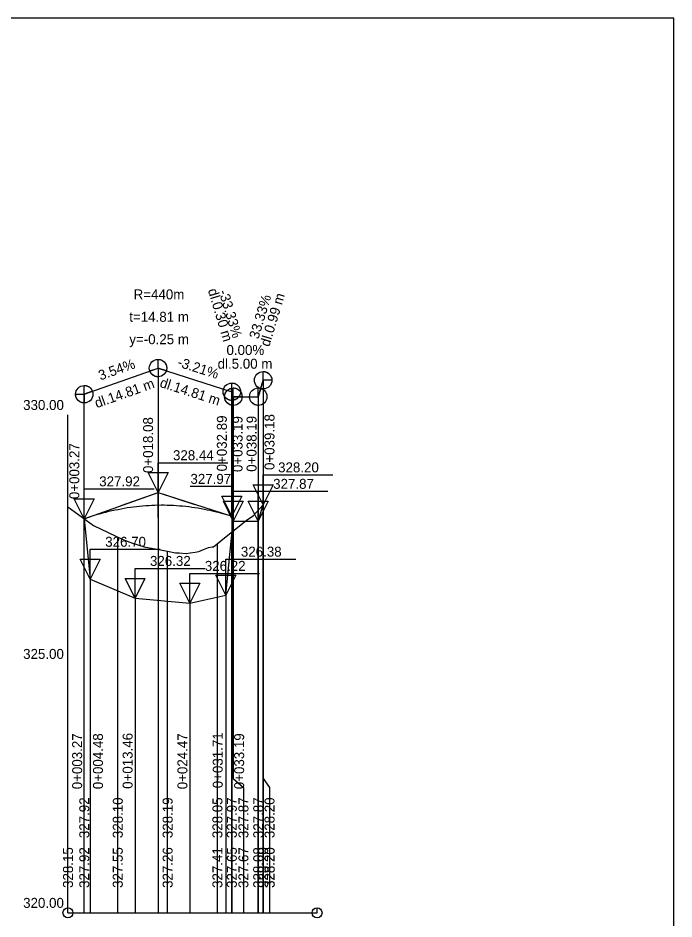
# Model space of a CAD drawing. Extents: x -559854 to -559644, y -1162908 to -1162611.
# Drawn here: x -559776.1 to -559644.4, y -1162791.6 to -1162610.6 of the extents above; entities that cross this region are included whole.
import ezdxf

# ---------------------------------------------------------------- set-up
doc = ezdxf.new("R2010")
doc.units = 0
for name, color, linetype in [('13', 7, 'Continuous'), ('14', 7, 'Continuous'), ('16', 7, 'Continuous'), ('46', 7, 'Continuous'), ('56', 7, 'Continuous'), ('8', 7, 'Continuous')]:
    doc.layers.add(name, color=color, linetype=linetype)

msp = doc.modelspace()

# ---------------------------------------------------------------- linework, layer by layer
for p, q in [((-559644.4, -1162610.63), (-559854.4, -1162610.63)), ((-559644.4, -1162907.63), (-559644.4, -1162610.63)), ((-559755.37, -1162708.56), (-559747.96, -1162705.94)), ((-559747.96, -1162710.94), (-559747.96, -1162705.94)), ((-559747.96, -1162705.94), (-559740.56, -1162708.31)), ((-559727.85, -1162711.69), (-559726.86, -1162708.38)), ((-559726.86, -1162790.35), (-559726.86, -1162708.35)), ((-559766.04, -1162790.35), (-559766.04, -1162708.85)), ((-559727.85, -1162790.35), (-559727.85, -1162709.55)), ((-559762.77, -1162790.35), (-559762.77, -1162711.15)), ((-559762.77, -1162790.35), (-559762.77, -1162711.15)), ((-559762.77, -1162711.19), (-559762.77, -1162711.19)), ((-559762.77, -1162711.19), (-559761.56, -1162723.33)), ((-559762.77, -1162711.19), (-559762.77, -1162711.19)), ((-559734.33, -1162726.55), (-559732.85, -1162711.69)), ((-559733.15, -1162710.69), (-559733.15, -1162710.69)), ((-559733.15, -1162710.69), (-559732.85, -1162711.69)), ((-559733.15, -1162710.69), (-559733.15, -1162710.69)), ((-559732.85, -1162711.69), (-559727.85, -1162711.69)), ((-559733.15, -1162790.35), (-559733.15, -1162713.85)), ((-559733.15, -1162790.35), (-559733.15, -1162713.85)), ((-559732.85, -1162763.37), (-559732.85, -1162713.65)), ((-559756.04, -1162790.35), (-559756.04, -1162714.85)), ((-559736.04, -1162790.35), (-559736.04, -1162716.25)), ((-559746.04, -1162790.35), (-559746.04, -1162717.75)), ((-559761.56, -1162723.33), (-559752.58, -1162727.17)), ((-559741.57, -1162728.17), (-559734.33, -1162726.55)), ((-559752.58, -1162727.17), (-559741.57, -1162728.17)), ((-559725.54, -1162790.35), (-559725.54, -1162765.15))]:
    msp.add_line(p, q)
for points in [[(-559766.04, -1162708.82), (-559760.9, -1162712.54), (-559755.05, -1162715.37), (-559753.07, -1162716.12), (-559753.07, -1162716.12), (-559750.72, -1162716.84), (-559747.47, -1162717.47), (-559745.74, -1162717.79), (-559744.46, -1162718.02), (-559744.01, -1162718.03), (-559743.74, -1162718.03), (-559742.34, -1162718.19), (-559742.27, -1162718.18), (-559741.5, -1162718.07), (-559740.54, -1162717.89), (-559739.78, -1162717.75), (-559738.81, -1162717.37), (-559737.82, -1162716.98), (-559737.07, -1162716.87), (-559736.83, -1162716.83), (-559735.34, -1162715.65), (-559730.26, -1162711.57), (-559728.82, -1162710.52), (-559727.58, -1162709.22), (-559726.82, -1162708.34)], [(-559762.77, -1162711.19), (-559762.15, -1162710.97), (-559761.54, -1162710.77), (-559760.92, -1162710.57), (-559760.3, -1162710.38), (-559759.68, -1162710.2), (-559759.07, -1162710.03), (-559758.45, -1162709.87), (-559757.83, -1162709.71), (-559757.22, -1162709.57), (-559756.6, -1162709.43), (-559755.98, -1162709.31), (-559755.37, -1162709.19), (-559754.75, -1162709.08), (-559754.13, -1162708.97), (-559753.51, -1162708.88), (-559752.9, -1162708.8), (-559752.28, -1162708.72), (-559751.66, -1162708.66), (-559751.05, -1162708.6), (-559750.43, -1162708.55), (-559749.81, -1162708.51), (-559749.19, -1162708.47), (-559748.58, -1162708.45), (-559747.34, -1162708.43), (-559746.73, -1162708.43), (-559746.11, -1162708.44), (-559745.49, -1162708.46), (-559744.87, -1162708.49), (-559744.26, -1162708.53), (-559743.64, -1162708.58), (-559743.02, -1162708.63), (-559742.41, -1162708.69), (-559741.79, -1162708.77), (-559741.17, -1162708.85), (-559740.56, -1162708.94), (-559739.94, -1162709.03), (-559739.32, -1162709.14), (-559738.7, -1162709.26), (-559738.09, -1162709.38), (-559737.47, -1162709.51), (-559736.85, -1162709.66), (-559736.24, -1162709.81), (-559735.62, -1162709.96), (-559735, -1162710.13), (-559734.38, -1162710.31), (-559733.77, -1162710.49), (-559733.15, -1162710.69)], [(-559762.77, -1162711.19), (-559762.15, -1162710.97), (-559761.54, -1162710.77), (-559760.92, -1162710.57), (-559760.3, -1162710.38), (-559759.68, -1162710.2), (-559759.07, -1162710.03), (-559758.45, -1162709.87), (-559757.83, -1162709.71), (-559757.22, -1162709.57), (-559756.6, -1162709.43), (-559755.98, -1162709.31), (-559755.37, -1162709.19), (-559754.75, -1162709.08), (-559754.13, -1162708.97), (-559753.51, -1162708.88), (-559752.9, -1162708.8), (-559752.28, -1162708.72), (-559751.66, -1162708.66), (-559751.05, -1162708.6), (-559750.43, -1162708.55), (-559749.81, -1162708.51), (-559749.19, -1162708.47), (-559748.58, -1162708.45), (-559747.34, -1162708.43), (-559746.73, -1162708.43), (-559746.11, -1162708.44), (-559745.49, -1162708.46), (-559744.87, -1162708.49), (-559744.26, -1162708.53), (-559743.64, -1162708.58), (-559743.02, -1162708.63), (-559742.41, -1162708.69), (-559741.79, -1162708.77), (-559741.17, -1162708.85), (-559740.56, -1162708.94), (-559739.94, -1162709.03), (-559739.32, -1162709.14), (-559738.7, -1162709.26), (-559738.09, -1162709.38), (-559737.47, -1162709.51), (-559736.85, -1162709.66), (-559736.24, -1162709.81), (-559735.62, -1162709.96), (-559735, -1162710.13), (-559734.38, -1162710.31), (-559733.77, -1162710.49), (-559733.15, -1162710.69)], [(-559725.54, -1162765.15), (-559726.82, -1162763.37), (-559726.82, -1162708.34)]]:
    msp.add_lwpolyline(points)
for centre in [(-559766.04, -1162790.35), (-559716.04, -1162790.35)]:
    msp.add_circle(centre, 1)
at = {"layer": '14'}
for p, q in [((-559762.77, -1162686.19), (-559747.96, -1162680.94)), ((-559747.96, -1162680.94), (-559747.96, -1162790.35)), ((-559747.96, -1162680.94), (-559733.15, -1162685.69)), ((-559727.85, -1162686.69), (-559726.86, -1162683.38)), ((-559726.86, -1162683.38), (-559726.86, -1162790.35)), ((-559762.77, -1162686.19), (-559762.77, -1162686.19)), ((-559733.15, -1162685.69), (-559733.15, -1162790.35)), ((-559733.15, -1162685.69), (-559732.85, -1162686.69)), ((-559732.85, -1162686.69), (-559732.85, -1162763.37)), ((-559732.85, -1162686.69), (-559727.85, -1162686.69)), ((-559727.85, -1162686.69), (-559727.85, -1162790.35)), ((-559762.77, -1162711.19), (-559747.96, -1162705.94)), ((-559747.96, -1162705.94), (-559747.96, -1162790.35)), ((-559747.96, -1162705.94), (-559733.15, -1162710.69)), ((-559727.85, -1162711.69), (-559726.86, -1162708.38)), ((-559727.85, -1162711.69), (-559726.86, -1162708.38)), ((-559727.85, -1162711.69), (-559726.86, -1162708.38)), ((-559726.86, -1162708.38), (-559726.86, -1162790.35)), ((-559762.77, -1162711.19), (-559761.56, -1162723.33)), ((-559762.77, -1162711.19), (-559762.77, -1162711.19)), ((-559762.77, -1162711.19), (-559762.77, -1162711.19)), ((-559762.77, -1162711.19), (-559762.77, -1162711.19)), ((-559762.77, -1162711.19), (-559761.56, -1162723.33)), ((-559762.77, -1162711.19), (-559762.77, -1162711.19)), ((-559762.77, -1162711.19), (-559761.56, -1162723.33)), ((-559734.33, -1162726.55), (-559732.85, -1162711.69)), ((-559734.33, -1162726.55), (-559732.85, -1162711.69)), ((-559734.33, -1162726.55), (-559732.85, -1162711.69)), ((-559733.15, -1162710.69), (-559733.15, -1162710.69)), ((-559733.15, -1162710.69), (-559732.85, -1162711.69)), ((-559733.15, -1162710.69), (-559733.15, -1162710.69)), ((-559733.15, -1162710.69), (-559732.85, -1162711.69)), ((-559733.15, -1162710.69), (-559733.15, -1162790.35)), ((-559733.15, -1162710.69), (-559732.85, -1162711.69)), ((-559732.85, -1162711.69), (-559727.85, -1162711.69)), ((-559732.85, -1162711.69), (-559727.85, -1162711.69)), ((-559732.85, -1162711.69), (-559732.85, -1162763.37)), ((-559732.85, -1162711.69), (-559727.85, -1162711.69)), ((-559732.85, -1162711.69), (-559732.85, -1162763.37)), ((-559727.85, -1162711.69), (-559727.85, -1162790.35)), ((-559761.56, -1162723.33), (-559752.58, -1162727.17)), ((-559761.56, -1162723.33), (-559761.56, -1162790.35)), ((-559761.56, -1162723.33), (-559752.58, -1162727.17)), ((-559741.57, -1162728.17), (-559734.33, -1162726.55)), ((-559741.57, -1162728.17), (-559734.33, -1162726.55)), ((-559734.33, -1162726.55), (-559734.33, -1162790.35)), ((-559752.58, -1162727.17), (-559741.57, -1162728.17)), ((-559752.58, -1162727.17), (-559752.58, -1162790.35)), ((-559752.58, -1162727.17), (-559741.57, -1162728.17)), ((-559741.57, -1162728.17), (-559741.57, -1162790.35))]:
    msp.add_line(p, q, dxfattribs=at)
for points in [[(-559762.77, -1162711.19), (-559762.15, -1162710.97), (-559761.54, -1162710.77), (-559760.92, -1162710.57), (-559760.3, -1162710.38), (-559759.68, -1162710.2), (-559759.07, -1162710.03), (-559758.45, -1162709.87), (-559757.83, -1162709.71), (-559757.22, -1162709.57), (-559756.6, -1162709.43), (-559755.98, -1162709.31), (-559755.37, -1162709.19), (-559754.75, -1162709.08), (-559754.13, -1162708.97), (-559753.51, -1162708.88), (-559752.9, -1162708.8), (-559752.28, -1162708.72), (-559751.66, -1162708.66), (-559751.05, -1162708.6), (-559750.43, -1162708.55), (-559749.81, -1162708.51), (-559749.19, -1162708.47), (-559748.58, -1162708.45), (-559747.34, -1162708.43), (-559746.73, -1162708.43), (-559746.11, -1162708.44), (-559745.49, -1162708.46), (-559744.87, -1162708.49), (-559744.26, -1162708.53), (-559743.64, -1162708.58), (-559743.02, -1162708.63), (-559742.41, -1162708.69), (-559741.79, -1162708.77), (-559741.17, -1162708.85), (-559740.56, -1162708.94), (-559739.94, -1162709.03), (-559739.32, -1162709.14), (-559738.7, -1162709.26), (-559738.09, -1162709.38), (-559737.47, -1162709.51), (-559736.85, -1162709.66), (-559736.24, -1162709.81), (-559735.62, -1162709.96), (-559735, -1162710.13), (-559734.38, -1162710.31), (-559733.77, -1162710.49), (-559733.15, -1162710.69)], [(-559732.85, -1162763.37), (-559730.82, -1162765.15), (-559730.82, -1162790.35)]]:
    msp.add_lwpolyline(points, dxfattribs=at)
at = {"layer": '16'}
msp.add_lwpolyline([(-559762.77, -1162711.19), (-559762.15, -1162710.97), (-559761.54, -1162710.77), (-559760.92, -1162710.57), (-559760.3, -1162710.38), (-559759.68, -1162710.2), (-559759.07, -1162710.03), (-559758.45, -1162709.87), (-559757.83, -1162709.71), (-559757.22, -1162709.57), (-559756.6, -1162709.43), (-559755.98, -1162709.31), (-559755.37, -1162709.19), (-559754.75, -1162709.08), (-559754.13, -1162708.97), (-559753.51, -1162708.88), (-559752.9, -1162708.8), (-559752.28, -1162708.72), (-559751.66, -1162708.66), (-559751.05, -1162708.6), (-559750.43, -1162708.55), (-559749.81, -1162708.51), (-559749.19, -1162708.47), (-559748.58, -1162708.45), (-559747.34, -1162708.43), (-559746.73, -1162708.43), (-559746.11, -1162708.44), (-559745.49, -1162708.46), (-559744.87, -1162708.49), (-559744.26, -1162708.53), (-559743.64, -1162708.58), (-559743.02, -1162708.63), (-559742.41, -1162708.69), (-559741.79, -1162708.77), (-559741.17, -1162708.85), (-559740.56, -1162708.94), (-559739.94, -1162709.03), (-559739.32, -1162709.14), (-559738.7, -1162709.26), (-559738.09, -1162709.38), (-559737.47, -1162709.51), (-559736.85, -1162709.66), (-559736.24, -1162709.81), (-559735.62, -1162709.96), (-559735, -1162710.13), (-559734.38, -1162710.31), (-559733.77, -1162710.49), (-559733.15, -1162710.69)], dxfattribs=at)
at = {"layer": '46'}
for points in [[(-559747.96, -1162680.94), (-559747.96, -1162679.19), (-559747.85, -1162679.19), (-559747.74, -1162679.2), (-559747.63, -1162679.22), (-559747.52, -1162679.24), (-559747.41, -1162679.28), (-559747.3, -1162679.31), (-559747.2, -1162679.36), (-559747.1, -1162679.41), (-559747.01, -1162679.47), (-559746.91, -1162679.53), (-559746.83, -1162679.6), (-559746.74, -1162679.68), (-559746.66, -1162679.76), (-559746.59, -1162679.85), (-559746.52, -1162679.94), (-559746.46, -1162680.03), (-559746.41, -1162680.13), (-559746.36, -1162680.23), (-559746.32, -1162680.33), (-559746.28, -1162680.44), (-559746.25, -1162680.55), (-559746.23, -1162680.66), (-559746.22, -1162680.77), (-559746.21, -1162680.88), (-559746.21, -1162680.99), (-559746.22, -1162681.1), (-559746.23, -1162681.22), (-559746.25, -1162681.33), (-559746.28, -1162681.43), (-559746.29, -1162681.47), (-559747.96, -1162680.94), (-559747.96, -1162682.69), (-559748.07, -1162682.68), (-559748.18, -1162682.67), (-559748.29, -1162682.65), (-559748.4, -1162682.63), (-559748.51, -1162682.6), (-559748.62, -1162682.56), (-559748.72, -1162682.51), (-559748.82, -1162682.46), (-559748.91, -1162682.4), (-559749.01, -1162682.34), (-559749.09, -1162682.27), (-559749.18, -1162682.19), (-559749.26, -1162682.11), (-559749.33, -1162682.03), (-559749.4, -1162681.94), (-559749.46, -1162681.84), (-559749.51, -1162681.75), (-559749.56, -1162681.64), (-559749.6, -1162681.54), (-559749.61, -1162681.52)], [(-559726.86, -1162683.38), (-559726.86, -1162681.63), (-559726.75, -1162681.64), (-559726.63, -1162681.65), (-559726.52, -1162681.66), (-559726.41, -1162681.69), (-559726.31, -1162681.72), (-559726.2, -1162681.76), (-559726.1, -1162681.81), (-559726, -1162681.86), (-559725.9, -1162681.92), (-559725.81, -1162681.98), (-559725.72, -1162682.05), (-559725.64, -1162682.13), (-559725.56, -1162682.21), (-559725.49, -1162682.29), (-559725.42, -1162682.38), (-559725.36, -1162682.48), (-559725.31, -1162682.57), (-559725.26, -1162682.67), (-559725.21, -1162682.78), (-559725.18, -1162682.88), (-559725.15, -1162682.99), (-559725.13, -1162683.1), (-559725.12, -1162683.21), (-559725.11, -1162683.33), (-559725.11, -1162683.38), (-559726.86, -1162683.38), (-559726.86, -1162685.13), (-559726.97, -1162685.13), (-559727.08, -1162685.12), (-559727.19, -1162685.1), (-559727.3, -1162685.08), (-559727.36, -1162685.06)], [(-559762.77, -1162686.19), (-559762.77, -1162684.44), (-559762.66, -1162684.44), (-559762.55, -1162684.45), (-559762.44, -1162684.47), (-559762.33, -1162684.49), (-559762.22, -1162684.53), (-559762.12, -1162684.57), (-559762.01, -1162684.61), (-559761.91, -1162684.66), (-559761.82, -1162684.72), (-559761.73, -1162684.78), (-559761.64, -1162684.85), (-559761.55, -1162684.93), (-559761.48, -1162685.01), (-559761.4, -1162685.1), (-559761.34, -1162685.19), (-559761.28, -1162685.28), (-559761.22, -1162685.38), (-559761.17, -1162685.48), (-559761.13, -1162685.58), (-559761.12, -1162685.6), (-559762.77, -1162686.19), (-559762.77, -1162687.94), (-559762.88, -1162687.93), (-559763, -1162687.92), (-559763.11, -1162687.9), (-559763.22, -1162687.88), (-559763.32, -1162687.85), (-559763.43, -1162687.81), (-559763.53, -1162687.76), (-559763.63, -1162687.71), (-559763.73, -1162687.65), (-559763.82, -1162687.59), (-559763.91, -1162687.52), (-559763.99, -1162687.44), (-559764.07, -1162687.36), (-559764.14, -1162687.28), (-559764.21, -1162687.19), (-559764.27, -1162687.09), (-559764.32, -1162687), (-559764.37, -1162686.9), (-559764.41, -1162686.79), (-559764.45, -1162686.69), (-559764.48, -1162686.58), (-559764.5, -1162686.47), (-559764.51, -1162686.36), (-559764.52, -1162686.24), (-559764.52, -1162686.19)], [(-559733.15, -1162685.69), (-559733.15, -1162683.94), (-559733.04, -1162683.94), (-559732.92, -1162683.95), (-559732.81, -1162683.97), (-559732.7, -1162683.99), (-559732.6, -1162684.03), (-559732.49, -1162684.07), (-559732.39, -1162684.11), (-559732.29, -1162684.16), (-559732.19, -1162684.22), (-559732.1, -1162684.28), (-559732.01, -1162684.35), (-559731.93, -1162684.43), (-559731.85, -1162684.51), (-559731.78, -1162684.6), (-559731.71, -1162684.69), (-559731.65, -1162684.78), (-559731.6, -1162684.88), (-559731.55, -1162684.98), (-559731.51, -1162685.08), (-559731.47, -1162685.19), (-559731.44, -1162685.3), (-559731.42, -1162685.41), (-559731.41, -1162685.52), (-559731.4, -1162685.63), (-559731.4, -1162685.74), (-559731.41, -1162685.86), (-559731.42, -1162685.97), (-559731.44, -1162686.08), (-559731.47, -1162686.19), (-559731.51, -1162686.29), (-559731.55, -1162686.4), (-559731.6, -1162686.5), (-559731.65, -1162686.59), (-559731.71, -1162686.69), (-559731.78, -1162686.78), (-559731.85, -1162686.86), (-559731.93, -1162686.94), (-559732.01, -1162687.02), (-559732.1, -1162687.09), (-559732.19, -1162687.15), (-559732.29, -1162687.21), (-559732.39, -1162687.26), (-559732.49, -1162687.31), (-559732.6, -1162687.35), (-559732.65, -1162687.36), (-559733.15, -1162685.69), (-559733.15, -1162687.44), (-559733.26, -1162687.43), (-559733.37, -1162687.42), (-559733.48, -1162687.4), (-559733.59, -1162687.38), (-559733.7, -1162687.35), (-559733.81, -1162687.31), (-559733.91, -1162687.26), (-559734.01, -1162687.21), (-559734.1, -1162687.15), (-559734.2, -1162687.09), (-559734.28, -1162687.02), (-559734.37, -1162686.94), (-559734.44, -1162686.86), (-559734.52, -1162686.78), (-559734.58, -1162686.69), (-559734.65, -1162686.59), (-559734.7, -1162686.5), (-559734.75, -1162686.4), (-559734.79, -1162686.29), (-559734.83, -1162686.19), (-559734.85, -1162686.08), (-559734.88, -1162685.97), (-559734.89, -1162685.86), (-559734.9, -1162685.74), (-559734.9, -1162685.63), (-559734.89, -1162685.52), (-559734.88, -1162685.41), (-559734.85, -1162685.3), (-559734.83, -1162685.19), (-559734.82, -1162685.15)], [(-559732.85, -1162686.69), (-559732.85, -1162684.94), (-559732.74, -1162684.94), (-559732.62, -1162684.95), (-559732.51, -1162684.97), (-559732.4, -1162684.99), (-559732.3, -1162685.03), (-559732.19, -1162685.07), (-559732.09, -1162685.11), (-559731.99, -1162685.16), (-559731.89, -1162685.22), (-559731.8, -1162685.28), (-559731.71, -1162685.35), (-559731.63, -1162685.43), (-559731.55, -1162685.51), (-559731.48, -1162685.6), (-559731.41, -1162685.69), (-559731.35, -1162685.78), (-559731.3, -1162685.88), (-559731.25, -1162685.98), (-559731.21, -1162686.08), (-559731.17, -1162686.19), (-559731.14, -1162686.3), (-559731.12, -1162686.41), (-559731.11, -1162686.52), (-559731.1, -1162686.63), (-559731.1, -1162686.69), (-559732.85, -1162686.69), (-559732.85, -1162688.44), (-559732.96, -1162688.43), (-559733.07, -1162688.42), (-559733.18, -1162688.4), (-559733.29, -1162688.38), (-559733.4, -1162688.35), (-559733.51, -1162688.31), (-559733.61, -1162688.26), (-559733.71, -1162688.21), (-559733.8, -1162688.15), (-559733.9, -1162688.09), (-559733.98, -1162688.02), (-559734.07, -1162687.94), (-559734.14, -1162687.86), (-559734.22, -1162687.78), (-559734.28, -1162687.69), (-559734.35, -1162687.59), (-559734.4, -1162687.5), (-559734.45, -1162687.4), (-559734.49, -1162687.29), (-559734.53, -1162687.19), (-559734.55, -1162687.08), (-559734.58, -1162686.97), (-559734.59, -1162686.86), (-559734.6, -1162686.74), (-559734.6, -1162686.63), (-559734.59, -1162686.52), (-559734.58, -1162686.41), (-559734.55, -1162686.3), (-559734.53, -1162686.19), (-559734.49, -1162686.08), (-559734.45, -1162685.98), (-559734.4, -1162685.88), (-559734.35, -1162685.78), (-559734.28, -1162685.69), (-559734.22, -1162685.6), (-559734.14, -1162685.51), (-559734.07, -1162685.43), (-559733.98, -1162685.35), (-559733.9, -1162685.28), (-559733.8, -1162685.22), (-559733.71, -1162685.16), (-559733.61, -1162685.11), (-559733.51, -1162685.07), (-559733.4, -1162685.03), (-559733.35, -1162685.01)], [(-559727.85, -1162686.69), (-559727.85, -1162684.94), (-559727.74, -1162684.94), (-559727.62, -1162684.95), (-559727.51, -1162684.97), (-559727.4, -1162684.99), (-559727.35, -1162685.01), (-559727.85, -1162686.69), (-559727.85, -1162688.44), (-559727.96, -1162688.43), (-559728.07, -1162688.42), (-559728.18, -1162688.4), (-559728.29, -1162688.38), (-559728.4, -1162688.35), (-559728.51, -1162688.31), (-559728.61, -1162688.26), (-559728.71, -1162688.21), (-559728.8, -1162688.15), (-559728.9, -1162688.09), (-559728.98, -1162688.02), (-559729.07, -1162687.94), (-559729.14, -1162687.86), (-559729.22, -1162687.78), (-559729.28, -1162687.69), (-559729.35, -1162687.59), (-559729.4, -1162687.5), (-559729.45, -1162687.4), (-559729.49, -1162687.29), (-559729.53, -1162687.19), (-559729.55, -1162687.08), (-559729.58, -1162686.97), (-559729.59, -1162686.86), (-559729.6, -1162686.74), (-559729.6, -1162686.69)], [(-559747.96, -1162705.94), (-559749.96, -1162701.94), (-559745.96, -1162701.94)], [(-559726.86, -1162708.38), (-559728.86, -1162704.38), (-559724.86, -1162704.38)], [(-559733.15, -1162710.69), (-559735.15, -1162706.69), (-559731.15, -1162706.69)], [(-559762.77, -1162711.19), (-559764.77, -1162707.19), (-559760.77, -1162707.19)], [(-559762.77, -1162711.19), (-559764.77, -1162707.19), (-559760.77, -1162707.19)], [(-559732.85, -1162711.69), (-559734.85, -1162707.69), (-559730.85, -1162707.69)], [(-559732.85, -1162711.69), (-559734.85, -1162707.69), (-559730.85, -1162707.69)], [(-559727.85, -1162711.69), (-559729.85, -1162707.69), (-559725.85, -1162707.69)], [(-559761.56, -1162723.33), (-559763.56, -1162719.33), (-559759.56, -1162719.33)], [(-559734.33, -1162726.55), (-559736.33, -1162722.55), (-559732.33, -1162722.55)], [(-559752.58, -1162727.17), (-559754.58, -1162723.17), (-559750.58, -1162723.17)], [(-559741.57, -1162728.17), (-559743.57, -1162724.17), (-559739.57, -1162724.17)]]:
    msp.add_lwpolyline(points, close=True, dxfattribs=at)
for centre in [(-559747.96, -1162680.94), (-559726.86, -1162683.38), (-559762.77, -1162686.19), (-559733.15, -1162685.69), (-559732.85, -1162686.69), (-559727.85, -1162686.69)]:
    msp.add_circle(centre, 1.75, dxfattribs=at)
at = {"layer": '56'}
for p, q in [((-559766.04, -1162790.35), (-559766.04, -1162690.35)), ((-559766.04, -1162790.35), (-559766.04, -1162789.35)), ((-559716.04, -1162790.35), (-559716.04, -1162789.35)), ((-559766.04, -1162790.35), (-559716.04, -1162790.35))]:
    msp.add_line(p, q, dxfattribs=at)
at = {"layer": '8'}
for p, q in [((-559762.77, -1162711.19), (-559762.77, -1162686.19)), ((-559733.15, -1162710.69), (-559733.15, -1162685.69)), ((-559747.96, -1162705.94), (-559747.96, -1162699.94)), ((-559747.96, -1162699.94), (-559733.96, -1162699.94)), ((-559726.86, -1162708.38), (-559726.86, -1162702.38)), ((-559726.86, -1162702.38), (-559712.86, -1162702.38)), ((-559741.53, -1162704.69), (-559733.15, -1162704.69)), ((-559733.15, -1162710.69), (-559733.15, -1162704.69)), ((-559762.77, -1162711.19), (-559762.77, -1162705.19)), ((-559762.77, -1162705.19), (-559748.77, -1162705.19)), ((-559762.77, -1162711.19), (-559762.77, -1162705.19)), ((-559762.77, -1162705.19), (-559748.77, -1162705.19)), ((-559732.85, -1162711.69), (-559732.85, -1162705.69)), ((-559732.85, -1162705.69), (-559718.85, -1162705.69)), ((-559732.85, -1162711.69), (-559732.85, -1162705.69)), ((-559732.85, -1162705.69), (-559718.85, -1162705.69)), ((-559727.85, -1162711.69), (-559727.85, -1162705.69)), ((-559727.85, -1162705.69), (-559713.85, -1162705.69)), ((-559761.56, -1162723.33), (-559761.56, -1162717.33)), ((-559761.56, -1162717.33), (-559747.56, -1162717.33)), ((-559734.33, -1162726.55), (-559734.33, -1162719.31)), ((-559734.33, -1162719.31), (-559720.33, -1162719.31)), ((-559752.58, -1162727.17), (-559752.58, -1162721.17)), ((-559752.58, -1162721.17), (-559738.58, -1162721.17)), ((-559741.57, -1162728.17), (-559741.57, -1162722.17)), ((-559741.57, -1162722.17), (-559727.57, -1162722.17))]:
    msp.add_line(p, q, dxfattribs=at)

# ---------------------------------------------------------------- texts
for s, p in [('327.92', (-559761.77, -1162775.35)), ('327.92', (-559761.77, -1162775.35)), ('328.10', (-559755.04, -1162775.35)), ('328.19', (-559745.04, -1162775.35)), ('328.05', (-559735.04, -1162775.35)), ('327.97', (-559732.15, -1162775.35)), ('327.97', (-559732.15, -1162775.35)), ('327.87', (-559729.82, -1162775.35)), ('327.87', (-559726.85, -1162775.35)), ('328.20', (-559724.58, -1162775.35)), ('328.15', (-559765.04, -1162785.35)), ('327.55', (-559755.04, -1162785.35)), ('327.26', (-559745.04, -1162785.35)), ('327.65', (-559732.15, -1162785.35)), ('327.65', (-559732.15, -1162785.35)), ('328.08', (-559726.85, -1162785.35)), ('328.20', (-559725.86, -1162785.35)), ('328.20', (-559724.58, -1162785.35)), ('328.20', (-559724.54, -1162785.35)), ('327.92', (-559761.77, -1162785.35)), ('327.92', (-559761.77, -1162785.35)), ('327.41', (-559735.04, -1162785.35)), ('327.67', (-559729.82, -1162785.35))]:
    msp.add_text(s, height=2, rotation=90).set_placement(p)
at = {"layer": '13'}
for s, p in [('330.00', (-559775.04, -1162689.35)), ('330.00', (-559775.04, -1162689.35)), ('325.00', (-559775.04, -1162739.35)), ('320.00', (-559775.04, -1162789.35))]:
    msp.add_text(s, height=2, dxfattribs=at).set_placement(p)
at = {"layer": '16'}
for s, rotation, p in [('dl.0.30 m', 286.6992, (-559737.98, -1162665.28)), ('-33.33%', 286.6992, (-559735.81, -1162665.54)), ('33.33%', 73.3008, (-559727.81, -1162675.24)), ('dl.0.99 m', 73.3008, (-559725.63, -1162676.77)), ('3.54%', 19.5194, (-559759.52, -1162683.44)), ('-3.21%', 342.2168, (-559744.23, -1162680.56)), ('dl.14.81 m', 342.2168, (-559747.75, -1162684.68)), ('dl.14.81 m', 19.5194, (-559760.26, -1162689.01)), ('0+039.18', 90, (-559724.59, -1162701.41)), ('0+018.08', 90, (-559748.96, -1162702.02)), ('0+032.89', 90, (-559734.15, -1162701.69)), ('0+033.19', 90, (-559731, -1162701.82)), ('0+038.19', 90, (-559728.19, -1162701.77)), ('0+003.27', 90, (-559763.77, -1162707.26)), ('0+003.27', 90, (-559763.2, -1162765.53)), ('0+004.48', 90, (-559759.02, -1162765.52)), ('0+013.46', 90, (-559753.07, -1162765.45)), ('0+024.47', 90, (-559742.07, -1162765.53)), ('0+031.71', 90, (-559734.98, -1162765.33)), ('0+033.19', 90, (-559730.68, -1162765.52))]:
    msp.add_text(s, height=2, rotation=rotation, dxfattribs=at).set_placement(p)
for s, p in [('R=440m', (-559752.86, -1162667.14)), ('t=14.81 m', (-559753.73, -1162671.64)), ('y=-0.25 m', (-559753.73, -1162676.14)), ('0.00%', (-559734.22, -1162678.31)), ('dl.5.00 m', (-559736, -1162681.07)), ('328.44', (-559744.96, -1162699.44)), ('328.20', (-559723.86, -1162701.88)), ('327.92', (-559759.77, -1162704.69)), ('327.92', (-559759.77, -1162704.69)), ('327.97', (-559741.46, -1162704.19)), ('327.87', (-559724.85, -1162705.19)), ('326.70', (-559758.56, -1162716.83)), ('326.38', (-559731.33, -1162718.81)), ('326.32', (-559749.58, -1162720.67)), ('326.22', (-559738.57, -1162721.67))]:
    msp.add_text(s, height=2, dxfattribs=at).set_placement(p)

doc.saveas('drawing.dxf')
